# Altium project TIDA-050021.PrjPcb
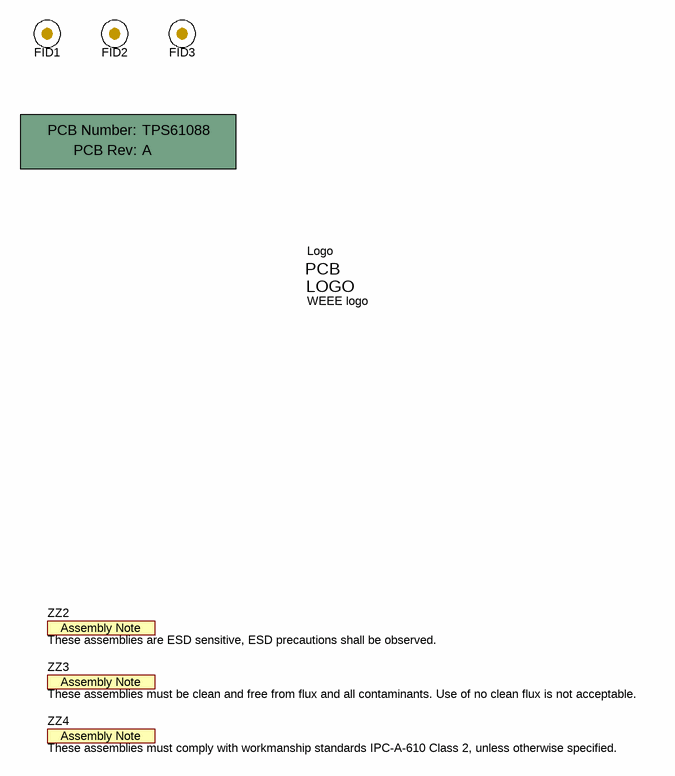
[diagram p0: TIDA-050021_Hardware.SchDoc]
CopyrightYear: 2017; PCB_Layout: Helen Chen; PCB_Rev: A; PRJ_Customer: Public Release; PRJ_Engineer: Helen Chen; PRJ_Number: TPS61088; PRJ_Title: TPS61088; SCH_Rev: A; TechSupport: http://www.ti.com/support; TID: N/A
2 sheets, 79 parts. Net scope: global (net labels, ports and power ports of the same name join across sheets).
Board file: TIDA-050021.PcbDoc
Sheets:
  TIDA-050021_Hardware.SchDoc
  TIDA-050021.SchDoc

## Sheet TIDA-050021_Hardware.SchDoc
size 431 x 279 mm; Date: Not shown in title block; ApprovedBy: Not shown in title block; CheckedBy: Not shown in title block; Author: Not shown in title block; CompanyName: Not shown in title block; Engineer: Not shown in title block; Organization: Not shown in title block; Address1: Not shown in title block; Address2: Not shown in title block; Address3: Not shown in title block; Address4: Not shown in title block; DocumentNumber: 1; Revision: Use project parameter SCH_Rev; SheetNumber: 3; SheetTotal: 3; PageSetup: Record=PageOptions¦CenterHorizontal=True¦CenterVertical=True¦PrintScale=1.00¦XCorrection=1.00¦YCorrection=1.00¦PrintKind=0¦BorderSize=5000000¦LeftOffset=0¦BottomOffset=0¦Orientation=2¦PaperLength=1000¦PaperWidth=1000¦Scale=100¦PaperSource=15¦PrintQuality=600¦MediaType=1¦DitherType=10¦PaperKind=Letter¦PrintScaleMode=1

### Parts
!PCB  Printed Circuit Board  (value not drawn)  (mechanical)
FID1  Fiducial  [Fiducial10-20]  (value not drawn)
FID2  Fiducial  [Fiducial10-20]  (value not drawn)
FID3  Fiducial  [Fiducial10-20]  (value not drawn)
Logo  WEEE logo  [WEEE_Minimum]  (no BOM)
ZZ2  These assemblies are ESD sensitive, ESD precautions shall be observed.  [AssemblyNote]  (no BOM)
ZZ3  These assemblies must be clean and free from flux and all contaminants. Use of no clean flux is not acceptable.  [AssemblyNote]  (no BOM)
ZZ4  These assemblies must comply with workmanship standards IPC-A-610 Class 2, unless otherwise specified.  [AssemblyNote]  (no BOM)

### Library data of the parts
!PCB = CMP-0003618-2: Manufacturer: Any; PartNumber: TPS61088
FID1-FID3 = CMP-0077181-1: Fiducial mark.  There is nothing to buy or mount.
Logo = CMP-0074769-1
ZZ2 = CMP-0077236-1
ZZ3 = CMP-0077237-1
ZZ4 = CMP-0077238-1

## Sheet TIDA-050021.SchDoc: TIDA-050021
size A3; Date: Not shown in title block; ApprovedBy: Not shown in title block; CheckedBy: Not shown in title block; Author: Not shown in title block; CompanyName: Not shown in title block; DrawnBy: Helen Chen; Engineer: Not shown in title block; Organization: Not shown in title block; Address1: Not shown in title block; Address2: Not shown in title block; Address3: Not shown in title block; Address4: Not shown in title block; DocumentNumber: 1; Revision: Use project parameter SCH_Rev; SheetNumber: 2; SheetTotal: 3; PageSetup: Record=PageOptions¦CenterHorizontal=True¦CenterVertical=True¦PrintScale=1.00¦XCorrection=1.00¦YCorrection=1.00¦PrintKind=0¦BorderSize=5000000¦LeftOffset=0¦BottomOffset=0¦Orientation=2¦PaperLength=1000¦PaperWidth=1000¦Scale=100¦PaperSource=15¦PrintQuality=600¦MediaType=1¦DitherType=10¦PaperKind=Letter¦PrintScaleMode=1
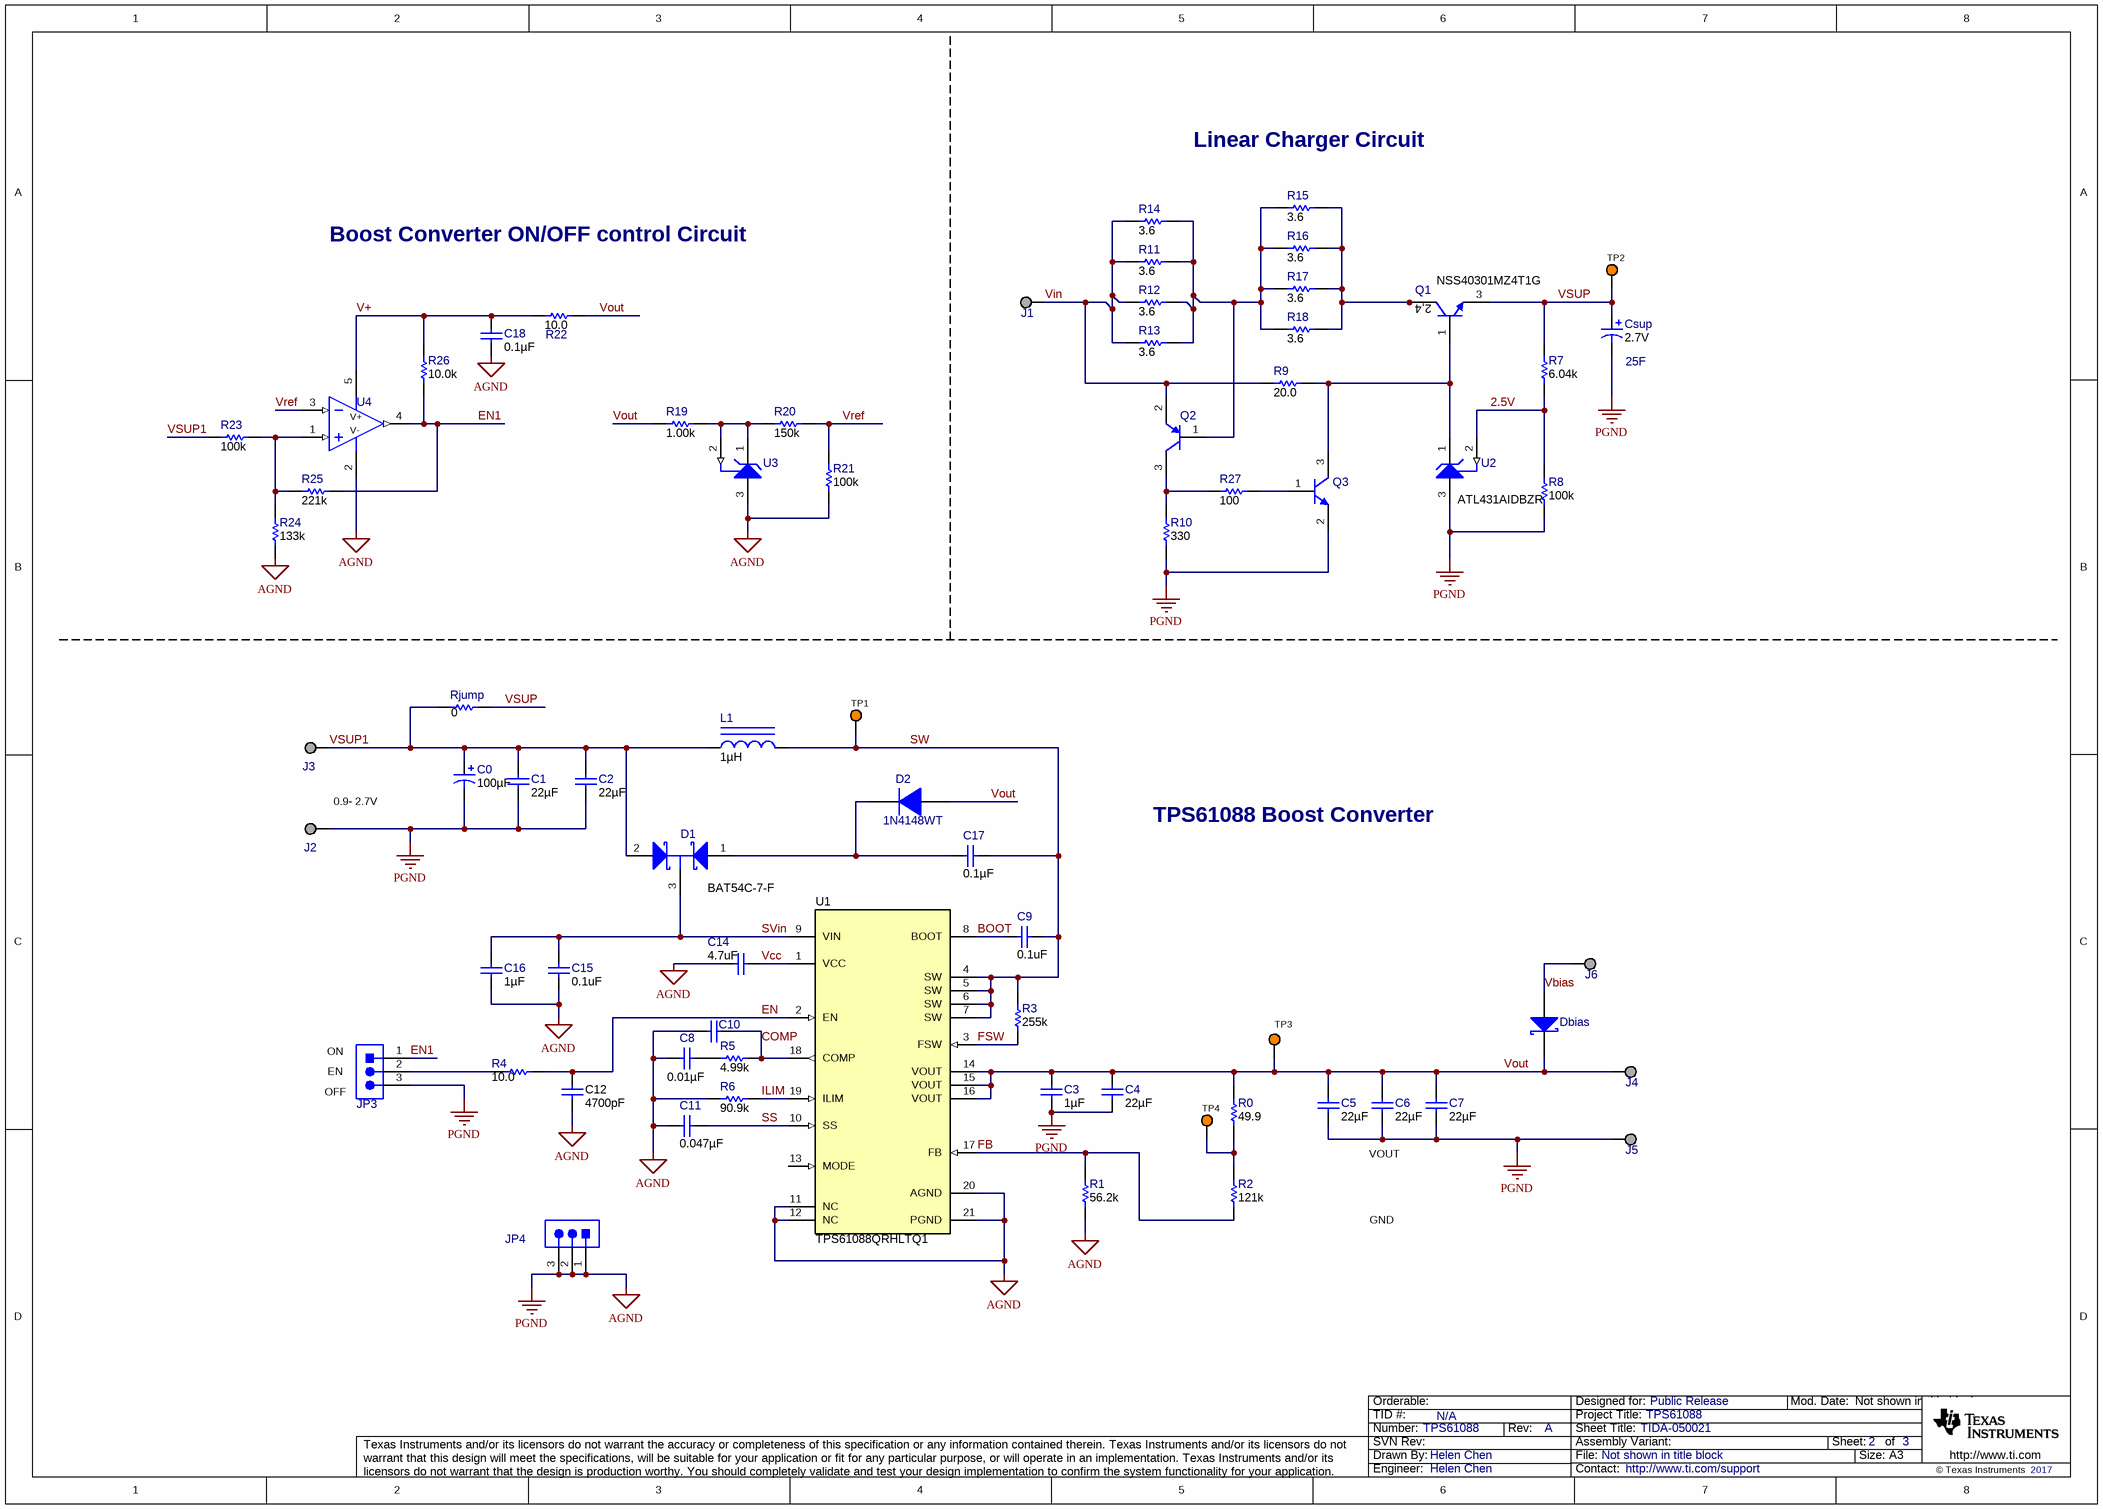
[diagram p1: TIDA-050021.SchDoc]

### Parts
C0  ValueDisplayed: 100µF  [7343-43]  (hidden comment: T495X107K016ATE100)
C1  ValueDisplayed: 22µF  [1206_180]  (hidden comment: GRM31CR61C226KE15L)
C2  ValueDisplayed: 22µF  [1206_180]  (hidden comment: GRM31CR61C226KE15L)
C3  ValueDisplayed: 1µF  [0603]  (hidden comment: GRM188R71E105KA12D)
C4  ValueDisplayed: 22µF  [1210_270]  (hidden comment: GRM32ER71E226KE15L)
C5  ValueDisplayed: 22µF  [1210_270]  (hidden comment: GRM32ER71E226KE15L)
C6  ValueDisplayed: 22µF  [1210_270]  (hidden comment: GRM32ER71E226KE15L)
C7  ValueDisplayed: 22µF  [1210_270]  (hidden comment: GRM32ER71E226KE15L)
C8  ValueDisplayed: 0.01µF  [0402]  (hidden comment: CGA2B3X7R1H103K050BB)
C9  ValueDisplayed: 0.1uF  [0402]  (hidden comment: GRM155R61C104KA88D)
C10  GRM1555C1H470FA01D  [0402]  (value not drawn)
C11  ValueDisplayed: 0.047µF  [0402]  (hidden comment: GRM155R71C473KA01D)
C12  ValueDisplayed: 4700pF  [0402]  (hidden comment: GRM155R61H472KA01D)
C14  ValueDisplayed: 4.7uF  [0603]  (hidden comment: 0603ZD475KAT2A)
C15  ValueDisplayed: 0.1uF  [0402]  (hidden comment: GRM155R61C104KA88D)
C16  ValueDisplayed: 1µF  [0603]  (hidden comment: GRM188R71E105KA12D)
C17  ValueDisplayed: 0.1µF  [0603]  (hidden comment: GRM188R61E104KA01D)
C18  ValueDisplayed: 0.1µF  [0402]  (hidden comment: GRM155R61A104KA01D)
Csup  VDC_V: 2.7V  [HV_1600x2840]  (hidden comment: HV1625-2R7256-R)
D1  BAT54C-7-F  [SOT-23]
D2  1N4148WT  [Fairchild_SOD-523F]
Dbias  MBRA210LT3G  [SMA]  (value not drawn)
J1  Suggest using a net name here  [Keystone1502-2]  (value not drawn)
J2  Suggest using a net name here  [Keystone1502-2]  (value not drawn)
J3  Suggest using a net name here  [Keystone1502-2]  (value not drawn)
J4  Suggest using a net name here  [Keystone1502-2]  (value not drawn)
J5  Suggest using a net name here  [Keystone1502-2]  (value not drawn)
J6  Suggest using a net name here  [Keystone1502-2]  (value not drawn)
JP3  PEC03SAAN  [CONN_PEC03SAAN]  (value not drawn)
JP4  PEC03SAAN  [CONN_PEC03SAAN]  (value not drawn)
L1  ValueDisplayed: 1µH  [XAL6030]  (hidden comment: XAL6030-102MEB)
Q1  NSS40301MZ4T1G  [SOT-223]
Q2  BC857C-7-F  [SOT-23]  (value not drawn)
Q3  BC847CLT1G  [SOT-23]  (value not drawn)
R0  value 49.9  [0402]  (hidden comment: CRCW040249R9FKED)
R1  ValueDisplayed: 56.2k  [0402]  (hidden comment: CRCW040256K2FKED)
R2  ValueDisplayed: 121k  [0402]  (hidden comment: CRCW0402121KFKED)
R3  ValueDisplayed: 255k  [0402]  (hidden comment: CRCW0402255KFKED)
R4  ValueDisplayed: 10.0  [0402]  (hidden comment: MCR01MZPF10R0)
R5  ValueDisplayed: 4.99k  [0402]  (hidden comment: CRCW04024K99FKED)
R6  ValueDisplayed: 90.9k  [0402]  (hidden comment: CRCW040290K9FKED)
R7  ValueDisplayed: 6.04k  [0402]  (hidden comment: CRCW04026K04FKED)
R8  ValueDisplayed: 100k  [0402]  (hidden comment: CRCW0402100KFKED)
R9  ValueDisplayed: 20.0  [1206]  (hidden comment: CRCW120620R0FKEAHP)
R10  ValueDisplayed: 330  [0402]  (hidden comment: ERJ-2RKF3300X)
R11  ValueDisplayed: 3.6  [1206]  (hidden comment: CRCW12063R60JNEA)
R12  ValueDisplayed: 3.6  [1206]  (hidden comment: CRCW12063R60JNEA)
R13  ValueDisplayed: 3.6  [1206]  (hidden comment: CRCW12063R60JNEA)
R14  ValueDisplayed: 3.6  [1206]  (hidden comment: CRCW12063R60JNEA)
R15  ValueDisplayed: 3.6  [1206]  (hidden comment: CRCW12063R60JNEA)
R16  ValueDisplayed: 3.6  [1206]  (hidden comment: CRCW12063R60JNEA)
R17  ValueDisplayed: 3.6  [1206]  (hidden comment: CRCW12063R60JNEA)
R18  ValueDisplayed: 3.6  [1206]  (hidden comment: CRCW12063R60JNEA)
R19  ValueDisplayed: 1.00k  [0402]  (hidden comment: CRCW04021K00FKED)
R20  ValueDisplayed: 150k  [0402]  (hidden comment: ERJ-2RKF1503X)
R21  ValueDisplayed: 100k  [0402]  (hidden comment: CRCW0402100KFKED)
R22  ValueDisplayed: 10.0  [0402]  (hidden comment: MCR01MZPF10R0)
R23  ValueDisplayed: 100k  [0402]  (hidden comment: CRCW0402100KFKED)
R24  ValueDisplayed: 133k  [0402]  (hidden comment: CRCW0402133KFKED)
R25  ValueDisplayed: 221k  [0402]  (hidden comment: CRCW0402221KFKED)
R26  ValueDisplayed: 10.0k  [0402]  (hidden comment: CRCW040210K0FKED)
R27  ValueDisplayed: 100  [0402]  (hidden comment: CRCW0402100RFKED)
Rjump  ValueDisplayed: 0  [2010]  (hidden comment: CRCW20100000Z0EF)
TP1  5003  [Keystone5003]  (value not drawn)
TP2  5003  [Keystone5003]  (value not drawn)
TP3  5003  [Keystone5003]  (value not drawn)
TP4  5003  [Keystone5003]  (value not drawn)
U1  TPS61088QRHLTQ1  [RHL0020A]
U2  ATL431AIDBZR  [DBZ0003A_N]
U3  ATL431AIDBZR  [DBZ0003A_N]  (value not drawn)
U4  LMV331IDBV  [DBV0005A_N]  (value not drawn)

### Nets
AGND: C0.2(-) C1.2 C2.2 C3.2 C4.2 C5.2 C6.2 C7.2 C8.2 C10.2 C11.1 C12.2 C14.1 C15.2 C16.2 C18.2 Csup.2(-) J2.1 J5.1 JP3.3 JP4.1 JP4.2 JP4.3 Q3.2(E) R1.1 R6.1 R8.1 R10.1 R21.1 R24.1 U1.11(NC) U1.12(NC) U1.20(AGND) U1.21(PGND) U2.3(ANODE) U3.3(ANODE) U4.2(V-)  [also labelled PGND]
2.5V: R7.1 R8.2 U2.2(REF)
BOOT: C9.2 U1.8(BOOT)
COMP: C10.1 R5.2 U1.18(COMP)
EN: C12.1 R4.2 U1.2(EN)
EN1: JP3.1 R25.2 R26.1 U4.4(OUT)
FB: R1.2 R2.1 U1.17(FB)
FSW: R3.1 U1.3(FSW)
ILIM: R6.2 U1.19(ILIM)
SS: C11.2 U1.10(SS)
SVin: C15.1 C16.1 D1.3(K) U1.9(VIN)
SW: C9.1 C17.1 L1.2 R3.2 TP1.1 U1.4(SW) U1.5(SW) U1.6(SW) U1.7(SW)
V+: C18.1 R22.1 R26.2 U4.5(V+)
Vbias: Dbias.2(A) J6.1
Vcc: C14.2 U1.1(VCC)
Vin: J1.1 Q2.2(E) R9.1 R11.1 R12.1 R13.1 R14.1
Vout: C3.1 C4.1 C5.1 C6.1 C7.1 D2.2(A) Dbias.1(K) J4.1 R0.2 R19.1 R22.2 TP3.1 U1.14(VOUT) U1.15(VOUT) U1.16(VOUT)
Vref: R20.2 R21.2 U4.3(IN-)
VSUP: Csup.1(+) Q1.3(E) R7.2 Rjump.2 TP2.1
VSUP1: C0.1(+) C1.1 C2.1 D1.2(A2) J3.1 L1.1 R23.2 Rjump.1
NetC8_1: C8.1 R5.1
NetC17_2: C17.2 D1.1(A1) D2.1(K)
NetJP3_2: JP3.2 R4.1
NetQ1_1: Q1.1(B) Q3.3(C) R9.2 U2.1(CATHODE)
NetQ1_2: Q1.2(C) Q1.4(C) R15.2 R16.2 R17.2 R18.2
NetQ2_1: Q2.1(B) R11.2 R12.2 R13.2 R14.2 R15.1 R16.1 R17.1 R18.1
NetQ2_3: Q2.3(C) R10.2 R27.1
NetQ3_1: Q3.1(B) R27.2
NetR0_1: R0.1 R2.2 TP4.1
NetR19_2: R19.2 R20.1 U3.1(CATHODE) U3.2(REF)
NetR23_1: R23.1 R24.2 R25.1 U4.1(IN+)

Not connected (* = marked no-connect by the designer): U1 13(MODE)

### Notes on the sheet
- Linear Charger Circuit
- Boost Converter ON/OFF control Circuit
- (near Csup) 25F
- (near J2) 0.9- 2.7V
- TPS61088 Boost Converter
- (near JP3) ON
- (near JP3) OFF
- (near JP3) EN
- VOUT
- GND

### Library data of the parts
C0 = T495X107K016ATE100: CAP, TA, 100 µF, 16 V, +/- 10%, 0.1 ohm, SMD; Manufacturer: Kemet; Polarized: Y; CompType: Capacitor; Value: 100uF; U/M: EA; Cap_F: 0.0001; Tolerance_%: 10; Value1: 0.1 ohm; VDC_V: 16; Value2: 16V; ESR_ohm: 0.1; IRMS_A: 1.156; TaMin_C: -55; TaMax_C: 125; Cap_Case: X
C1 C2 = GRM31CR61C226KE15L: CAP, CERM, 22 µF, 16 V,+/- 10%, X5R, 1206; Manufacturer: MuRata; Polarized: N; CompType: Capacitor; Value: 22uF; U/M: EA; Cap_F: 0.000022; Tolerance_%: 10; VDC_V: 16; Value2: 16V; TaMin_C: -55; TaMax_C: 85; Cap_Case: 1206; SizeArea_mm2: 5.12; SizeAreaWB_mm2: 10.92; SizeX_mm: 3.2; SizeY_mm: 1.6; SizeZ_mm: 1.8; AEC Category: Q200; Green_Lifecycle: Active; Green_REACh: Passed
C3 C16 = GRM188R71E105KA12D: CAP, CERM, 1 µF, 25 V, +/- 10%, X7R, 0603; Manufacturer: MuRata; Polarized: N; CompType: Capacitor; Value: 1uF; U/M: EA; Cap_F: 0.000001; Tolerance_%: 10; Value1: Unknown; VDC_V: 25; Value2: 25V; TaMin_C: -55; TaMax_C: 125
C4-C7 = GRM32ER71E226KE15L: CAP, CERM, 22 µF, 25 V,+/- 10%, X7R, 1210; Manufacturer: MuRata; Polarized: N; CompType: Capacitor; Value: 22uF; U/M: EA; Cap_F: 0.000022; Tolerance_%: 10; ESR_ohm: 0.002334; Value1: 0.002334 ohm; VDC_V: 25; Value2: 25V; IRMS_A: 3.832999; TaMin_C: -55; TaMax_C: 125; Cap_Case: 1210; SizeArea_mm2: 8; SizeAreaWB_mm2: 14.7; SizeX_mm: 3.2; SizeY_mm: 2.5; SizeZ_mm: 2.7; AEC Category: Q200; Green_Lifecycle: Active; Green_REACh: Passed
C8 = CGA2B3X7R1H103K050BB: CAP, CERM, 0.01 µF, 50 V,+/- 10%, X7R, AEC-Q200 Grade 1, 0402; Manufacturer: TDK; Polarized: N; CompType: Capacitor; Value: 0.01uF; U/M: EA; Cap_F: 0.00000001; Tolerance_%: 10; ESR_ohm: 0.333065; Value1: 0.333065 ohm; VDC_V: 50; Value2: 50V; IRMS_A: 0.323373; TaMin_C: -55; TaMax_C: 125; SizeArea_mm2: 0.5; SizeAreaWB_mm2: 3; SizeX_mm: 1; SizeZ_mm: 0.6; AEC Category: Q200; AEC Qualified: Y; Green_Lifecycle: Active; Green_REACh: Passed
C9 C15 = GRM155R61C104KA88D: CAP, CERM, 0.1uF, 16V, +/-10%, X5R, 0402; Manufacturer: MuRata; Polarized: N; CompType: Capacitor; U/M: EA; Cap_F: 0.0000001; Tolerance_%: 10; Value1: Unknown; VDC_V: 16; TaMin_C: -55; TaMax_C: 85
C10 = GRM1555C1H470FA01D: CAP, CERM, 47 pF, 50 V, +/- 1%, C0G, 0402; Manufacturer: MuRata; Polarized: N; CompType: Capacitor; Value: 47pF; U/M: EA; Cap_F: 0.000000000047; Tolerance_%: 1; Value1: Unknown; VDC_V: 50; Value2: 50V; TaMin_C: -55; TaMax_C: 125
C11 = GRM155R71C473KA01D: CAP, CERM, 0.047 µF, 16 V, +/- 10%, X7R, 0402; Manufacturer: MuRata; Polarized: N; CompType: Capacitor; Value: 0.047uF; U/M: EA; Cap_F: 0.000000047; Tolerance_%: 10; Value1: Unknown; VDC_V: 16; Value2: 16V; TaMin_C: -55; TaMax_C: 125
C12 = GRM155R61H472KA01D: CAP, CERM, 4700 pF, 50 V, +/- 10%, X5R, 0402; Manufacturer: MuRata; Polarized: N; CompType: Capacitor; Value: 4700pF; U/M: EA; Cap_F: 0.0000000047; Tolerance_%: 10; Value1: Unknown; VDC_V: 50; Value2: 50V; TaMin_C: -55; TaMax_C: 85
C14 = 0603ZD475KAT2A: CAP, CERM, 4.7uF, 10V, +/-10%, X5R, 0603; Manufacturer: AVX; Polarized: N; CompType: Capacitor; U/M: EA; Cap_F: 0.0000047; Tolerance_%: 10; Value1: Unknown; TaMin_C: -55; TaMax_C: 85
C17 = GRM188R61E104KA01D: CAP, CERM, 0.1 µF, 25 V,+/- 10%, X5R, 0603; Manufacturer: MuRata; Polarized: N; CompType: Capacitor; Value: 0.1uF; U/M: EA; Cap_F: 0.0000001; Tolerance_%: 10; VDC_V: 25; Value2: 25V; TaMin_C: -55; TaMax_C: 85; SizeArea_mm2: 1.28; SizeAreaWB_mm2: 4.68; SizeX_mm: 1.6; SizeY_mm: 0.8; SizeZ_mm: 1; AEC Category: Q200; Green_Lifecycle: Active; Green_REACh: Passed
C18 = GRM155R61A104KA01D: CAP, CERM, 0.1 µF, 10 V,+/- 10%, X5R, 0402; Manufacturer: MuRata; Polarized: N; CompType: Capacitor; Value: 0.1uF; U/M: EA; Cap_F: 0.0000001; Tolerance_%: 10; Value2: 10V; TaMin_C: -55; TaMax_C: 85; SizeArea_mm2: 0.5; SizeAreaWB_mm2: 3; SizeX_mm: 1; SizeZ_mm: 0.6; AEC Category: Q200; Green_Lifecycle: Active; Green_REACh: Passed
Csup = CMP-0084049-1: CAP, Electric Double Layer, 25000000 µF, 2.7 V,+30/-10%, 0.027 ohm, TH; Manufacturer: Eaton; TaMin_C: -40°C; ESR_ohm: 0.027; Polarized: Y; SizeAreaWB_mm2: 324; Value: 25000000uF; TaMax_C: 65°C; Tolerance_%: 30%; SizeZ_mm: 28.4; SizeX_mm: 16; Cap_Case: 16x28.4mm; SizeArea_mm2: 256; CompType: Capacitor; AEC Qualified: N; Cap_F: 25F; AEC Category: Q200
D1 = BAT54C-7-F: Diode, Schottky, 30 V, 0.2 A, SOT-23; Manufacturer: Diodes Inc.; U/M: EA; Vf_V: 0.65; Value: 30V; Value1: 0.2A; Value2: 0.65V; Io_A: 0.2; Vr_V: 30; TJmax_C: 125; SizeAreaWB_mm2: 14; SizeArea_mm2: 7.5; SizeX_mm: 2.5; SizeY_mm: 3; SizeZ_mm: 1.1; AEC Category: Q101; Green_Lifecycle: Active; Green_REACh: Passed
D2 = 1N4148WT: Diode, Switching, 75 V, 0.3 A, SMD, 2-Leads, Body 1.2x0.8mm; Manufacturer: Fairchild Semiconductor; U/M: EA; Value: 75V; Value1: 0.3A; Io_A: 0.3; Vr_V: 75; TJmax_C: 150
Dbias = MBRA210LT3G: Diode, Schottky, 10 V, 2 A, SMA; Manufacturer: ON Semiconductor; U/M: EA; Vf_V: 0.35; Value: 10V; Value1: 2A; Value2: 0.35V; Io_A: 2; Vr_V: 10; TJmax_C: 125; RJC_CperW: 22; SizeAreaWB_mm2: 37.3428; SizeArea_mm2: 16.3228; SizeX_mm: 5.59; SizeY_mm: 2.92; SizeZ_mm: 2.87; AEC Category: Q101; Green_Lifecycle: Not Set; Green_REACh: Incomplete
J1-J6 = 1502-2: Terminal, Turret, TH, Double; Manufacturer: Keystone; CompType: Turret Terminal; U/M: EA
JP3 JP4 = PEC03SAAN: Header, 100mil, 3x1, Tin, TH; Manufacturer: Sullins Connector Solutions; SymbolCreator: a0412235; Pitch_mm: 2.54; Gender: Male; Shrouded: N; Row_Count: 1; Current_A: 3; Voltage_V: 1800; Cert_UL: Y; Green_Lifecycle: Not Set; Green_REACh: Incomplete
L1 = XAL6030-102MEB: Inductor, Shielded, Composite, 1 µH, 21.5 A, 0.01 ohm, SMD; Manufacturer: Coilcraft; Value: 1uH; Ind_H: 1.0E-6; Imax_A: 21.5; Irms: 21.5A @ 40C rise; Isat: 23A @ 30% inductance drop; DCR_ohm: 0.01; Value2: 21.5A; SizeAreaWB_mm2: 71.5616; SizeArea_mm2: 41.7216; SizeX_mm: 6.36; SizeY_mm: 6.56; SizeZ_mm: 3.1; AEC Category: Q200; Green_Lifecycle: Not Set; Green_REACh: Incomplete
Q1 = NSS40301MZ4T1G, ON Semiconductor: Transistor, NPN, 40 V, 3 A, SOT-223; SymbolCreator: a0412235; PNP: 0; NPN: 1; Vceo_V: 40; Vcesat1_V: 0.2; Value: 40 V; IcRated_A: 3; Value1: 3 A; HfeMax: 500; TaMin_C: -55; TaMax_C: 150; SizeAreaWB_mm2: 76.5; SizeArea_mm2: 45.5; SizeX_mm: 6.5; SizeY_mm: 7; SizeZ_mm: 1.6; CompType: BJT; U/M: EA; AEC Category: Q101
Q2 = BC857C-7-F, Diodes Inc.: Transistor, PNP, 45 V, 0.1 A, SOT-23; CompType: BJT; PNP: 1; NPN: 0; Vceo_V: 45; Vcesat1_V: 0.075; Value: 45 V; IcRated_A: 0.1; Value1: 0.1 A; HfeMax: 600; TaMin_C: -65; TaMax_C: 150; SizeAreaWB_mm2: 14; SizeArea_mm2: 7.5; SizeX_mm: 2.5; SizeY_mm: 3; SizeZ_mm: 1.1; U/M: EA; AEC Category: Q101
Q3 = BC847CLT1G, ON Semiconductor: Transistor, NPN, 45 V, 0.1 A, SOT-23; CompType: BJT; PNP: 0; NPN: 1; Vceo_V: 45; Vcesat1_V: 0.7; Value: 45 V; IcRated_A: 0.1; Value1: 0.1 A; HfeMax: 800; TaMin_C: -55; TaMax_C: 150; SizeAreaWB_mm2: 14; SizeArea_mm2: 7.5; SizeX_mm: 2.5; SizeY_mm: 3; SizeZ_mm: 1.1; U/M: EA; AEC Category: Q101; Green_Lifecycle: Active; Green_REACh: Passed
R0 = CRCW040249R9FKED: RES, 49.9 ohm, 1%, 0.063W, 0402; Manufacturer: Vishay-Dale; CompType: Resistor; Value_Code: 49R9; Tolerance_%: 1; Power_W: 0.063; VDC_V: 50; TempCo: 100 ppm/C; EIA_Code: E96; U/M: EA
R1 = CRCW040256K2FKED: RES, 56.2 k, 1%, 0.063 W, 0402; Manufacturer: Vishay-Dale; CompType: Resistor; Value: 56.2k; Res_ohm: 56200; Value_Code: 56k2; Tolerance_%: 1; Power_W: 0.063; Value2: 0.063W; VDC_V: 50; TempCo: 100 ppm/C; SizeArea_mm2: 0.5; SizeZ_mm: 0.6; EIA_Code: E96; U/M: EA; AEC Category: Q200; Green_Lifecycle: Active; Green_REACh: Passed
R2 = CRCW0402121KFKED: RES, 121 k, 1%, 0.063 W, 0402; Manufacturer: Vishay-Dale; CompType: Resistor; Value: 121k; Res_ohm: 121000; Tolerance_%: 1; Power_W: 0.063; Value2: 0.063W; VDC_V: 50; TempCo: 100 ppm/C; SizeArea_mm2: 0.5; SizeZ_mm: 0.6; EIA_Code: E96; U/M: EA; AEC Category: Q200; Green_Lifecycle: Active; Green_REACh: Passed
R3 = CRCW0402255KFKED: RES, 255 k, 1%, 0.063 W, 0402; Manufacturer: Vishay-Dale; CompType: Resistor; Value: 255k; Res_ohm: 255000; Tolerance_%: 1; Power_W: 0.063; Value2: 0.063W; VDC_V: 50; TempCo: 100 ppm/C; SizeArea_mm2: 0.5; SizeZ_mm: 0.6; EIA_Code: E96; U/M: EA; AEC Category: Q200; Green_Lifecycle: Active; Green_REACh: Passed
R4 R22 = MCR01MZPF10R0: RES, 10.0, 1%, 0.063 W, 0402; Manufacturer: Rohm; CompType: Resistor; Value: 10.0; Res_ohm: 10; Value_Code: 10R0; Tolerance_%: 1; Power_W: 0.063; Value2: 0.063W; VDC_V: 50; TempCo: 100 ppm/C; SizeArea_mm2: 0.5; SizeZ_mm: 0.6; EIA_Code: E96; U/M: EA; AEC Category: Q200; AEC Qualified: N
R5 = CRCW04024K99FKED: RES, 4.99 k, 1%, 0.063 W, 0402; Manufacturer: Vishay-Dale; CompType: Resistor; Value: 4.99k; Res_ohm: 4990; Value_Code: 4k99; Tolerance_%: 1; Power_W: 0.063; Value2: 0.063W; VDC_V: 50; TempCo: 100 ppm/C; SizeArea_mm2: 0.5; SizeZ_mm: 0.6; EIA_Code: E96; U/M: EA; AEC Category: Q200; Green_Lifecycle: Active; Green_REACh: Passed
R6 = CRCW040290K9FKED: RES, 90.9 k, 1%, 0.063 W, 0402; Manufacturer: Vishay-Dale; CompType: Resistor; Value: 90.9k; Res_ohm: 90900; Value_Code: 90k9; Tolerance_%: 1; Power_W: 0.063; Value2: 0.063W; VDC_V: 50; TempCo: 100 ppm/C; SizeArea_mm2: 0.5; SizeZ_mm: 0.6; EIA_Code: E96; U/M: EA; AEC Category: Q200; Green_Lifecycle: Active; Green_REACh: Passed
R7 = CRCW04026K04FKED: RES, 6.04 k, 1%, 0.063 W, 0402; Manufacturer: Vishay-Dale; CompType: Resistor; Value: 6.04k; Res_ohm: 6040; Value_Code: 6k04; Tolerance_%: 1; Power_W: 0.063; Value2: 0.063W; VDC_V: 50; TempCo: 100 ppm/C; SizeArea_mm2: 0.5; SizeZ_mm: 0.6; EIA_Code: E96; U/M: EA; AEC Category: Q200; Green_Lifecycle: Active; Green_REACh: Passed
R8 R21 R23 = CRCW0402100KFKED: RES, 100 k, 1%, 0.063 W, 0402; Manufacturer: Vishay-Dale; CompType: Resistor; Value: 100k; Res_ohm: 100000; Tolerance_%: 1; Power_W: 0.063; Value2: 0.063W; VDC_V: 50; TempCo: 100 ppm/C; SizeArea_mm2: 0.5; SizeZ_mm: 0.6; EIA_Code: E96; U/M: EA; AEC Category: Q200; Green_Lifecycle: Active; Green_REACh: Passed
R9 = CRCW120620R0FKEAHP: RES, 20.0, 1%, 0.5 W, AEC-Q200 Grade 0, 1206; Manufacturer: Vishay-Dale; CompType: Resistor; Value: 20.0; Res_ohm: 20; Value_Code: 20R0; Tolerance_%: 1; Power_W: 0.5; Value2: 0.5W; TempCo: 100 ppm/C; SizeArea_mm2: 5.12; SizeX_mm: 3.2; SizeY_mm: 1.6; SizeZ_mm: 1.35; EIA_Code: E96; U/M: EA; AEC Category: Q200; AEC Qualified: Y; AEC Grade: 0
R10 = ERJ-2RKF3300X: RES, 330, 1%, 0.1 W, AEC-Q200 Grade 0, 0402; Manufacturer: Panasonic; CompType: Resistor; Value: 330; Value_Code: 330R; Tolerance_%: 1; Power_W: 0.1; Value2: 0.1W; VDC_V: 50; TempCo: 100 ppm/C; SizeArea_mm2: 0.5; SizeZ_mm: 0.6; U/M: EA; AEC Category: Q200; AEC Qualified: Y; AEC Grade: 0; Green_Lifecycle: Active; Green_REACh: Passed
R11-R18 = CRCW12063R60JNEA: RES, 3.6, 5%, 0.25 W, 1206; Manufacturer: Vishay-Dale; CompType: Resistor; Value: 3.6; Value_Code: 3R60; Tolerance_%: 5; Power_W: 0.25; Value2: 0.25W; VDC_V: 200; TempCo: 200 ppm/C; SizeArea_mm2: 5.12; SizeX_mm: 3.2; SizeY_mm: 1.6; SizeZ_mm: 1.35; EIA_Code: E24; U/M: EA; AEC Category: Q200
R19 = CRCW04021K00FKED: RES, 1.00 k, 1%, 0.063 W, 0402; Manufacturer: Vishay-Dale; CompType: Resistor; Value: 1.00k; Res_ohm: 1000; Value_Code: 1k00; Tolerance_%: 1; Power_W: 0.063; Value2: 0.063W; VDC_V: 50; TempCo: 100 ppm/C; SizeArea_mm2: 0.5; SizeZ_mm: 0.6; EIA_Code: E96; U/M: EA; AEC Category: Q200; Green_Lifecycle: Active; Green_REACh: Passed
R20 = ERJ-2RKF1503X: RES, 150 k, 1%, 0.1 W, AEC-Q200 Grade 0, 0402; Manufacturer: Panasonic; CompType: Resistor; Value: 150k; Res_ohm: 150000; Tolerance_%: 1; Power_W: 0.1; Value2: 0.1W; VDC_V: 50; TempCo: 100 ppm/C; SizeArea_mm2: 0.5; SizeZ_mm: 0.6; EIA_Code: E96; U/M: EA; AEC Category: Q200; AEC Qualified: Y; AEC Grade: 0; Green_Lifecycle: Active; Green_REACh: Passed
R24 = CRCW0402133KFKED: RES, 133 k, 1%, 0.063 W, 0402; Manufacturer: Vishay-Dale; CompType: Resistor; Value: 133k; Res_ohm: 133000; Tolerance_%: 1; Power_W: 0.063; Value2: 0.063W; VDC_V: 50; TempCo: 100 ppm/C; SizeArea_mm2: 0.5; SizeZ_mm: 0.6; EIA_Code: E96; U/M: EA; AEC Category: Q200; Green_Lifecycle: Active; Green_REACh: Passed
R25 = CRCW0402221KFKED: RES, 221 k, 1%, 0.063 W, 0402; Manufacturer: Vishay-Dale; CompType: Resistor; Value: 221k; Res_ohm: 221000; Tolerance_%: 1; Power_W: 0.063; Value2: 0.063W; VDC_V: 50; TempCo: 100 ppm/C; SizeArea_mm2: 0.5; SizeZ_mm: 0.6; EIA_Code: E96; U/M: EA; AEC Category: Q200
R26 = CRCW040210K0FKED: RES, 10.0 k, 1%, 0.063 W, 0402; Manufacturer: Vishay-Dale; CompType: Resistor; Value: 10.0k; Res_ohm: 10000; Value_Code: 10k0; Tolerance_%: 1; Power_W: 0.063; Value2: 0.063W; VDC_V: 50; TempCo: 100 ppm/C; SizeArea_mm2: 0.5; SizeZ_mm: 0.6; EIA_Code: E96; U/M: EA; AEC Category: Q200; Green_Lifecycle: Active; Green_REACh: Passed
R27 = CRCW0402100RFKED: RES, 100, 1%, 0.063 W, 0402; Manufacturer: Vishay-Dale; CompType: Resistor; Value: 100; Value_Code: 100R; Tolerance_%: 1; Power_W: 0.063; Value2: 0.063W; VDC_V: 50; TempCo: 100 ppm/C; SizeArea_mm2: 0.5; SizeZ_mm: 0.6; EIA_Code: E96; U/M: EA; AEC Category: Q200; Green_Lifecycle: Active; Green_REACh: Passed
Rjump = CRCW20100000Z0EF: RES, 0, 5%, 0.75 W, AEC-Q200 Grade 0, 2010; Manufacturer: Vishay-Dale; CompType: Resistor; Value: 0; Value_Code: 0000; Tolerance_%: 5; Power_W: 0.75; Value2: 0.75W; TempCo: ppm/C; SizeArea_mm2: 12.5; SizeY_mm: 2.5; SizeZ_mm: 1.66; EIA_Code: E24; U/M: EA; AEC Category: Q200; AEC Qualified: Y
TP1-TP4 = 5003: Test Point, Miniature, Orange, TH; Manufacturer: Keystone; CompType: Test Point Loop; U/M: EA
U1 = CMP-0082346-1: 10-A Fully-Integrated Synchronous Boost Converter, RHL0020A (VQFN-20); Alternate PartNumber: TPS61088QRHLRQ1; Alternate Manufacturer: Texas Instruments; SizeAreaWB_mm2: 24.75; Rating: Automotive; SizeZ_mm: 1; SizeX_mm: 4.5; SizeY_mm: 3.5; SizeArea_mm2: 15.75; CompType: IC; AEC Qualified: Y; AEC Category: Q200
U2 U3 = ATL431AIDBZR: 2.5V Low Iq Adjustable Precision Shunt Regulator, DBZ0003A (SOT-23-3); Manufacturer: Texas Instruments; SymbolCreator: a0412235; SizeArea_mm2: 7.5; SizeAreaWB_mm2: 14; SizeX_mm: 2.5; SizeY_mm: 3; SizeZ_mm: 1.12; CompType: IC; U/M: EA
U4 = LMV331IDBV: Single General Purpose Low-Voltage Comparator, DBV0005A; Manufacturer: Texas Instruments; SymbolCreator: a0411595; CompType: OpAmp IC

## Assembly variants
001: not fitted C0 C12 C13 FID1 FID2 FID3 R7 R8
